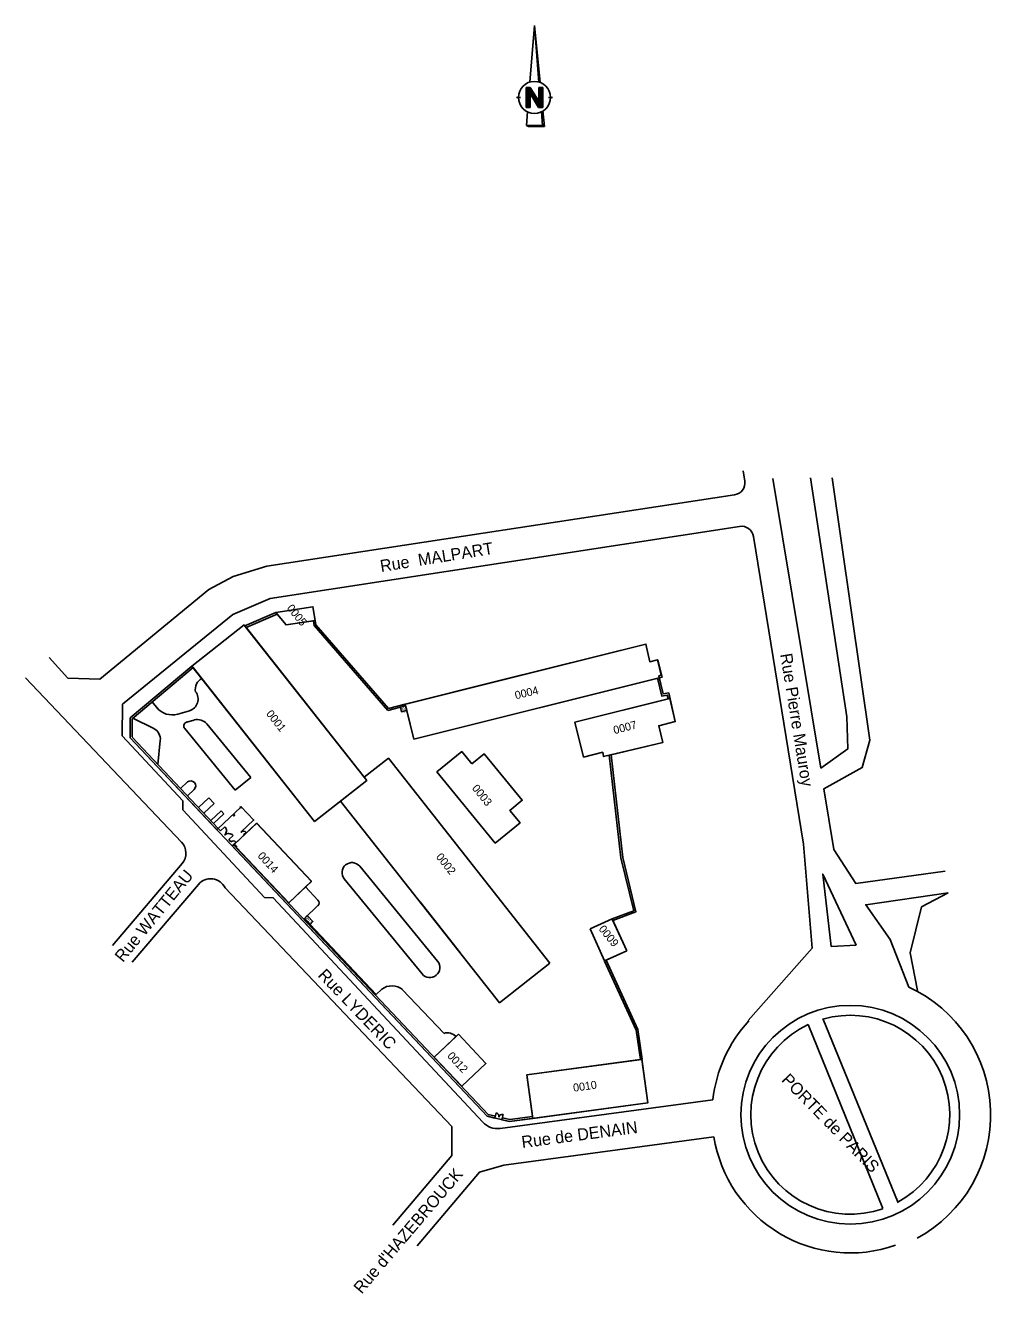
# Model space of a CAD drawing. Extents: x 704383 to 706615, y 7057567 to 7059313.
# Drawn here: x 704383.3 to 704624.5, y 7058894 to 7059210.9 of the extents above; entities that cross this region are included whole.
import ezdxf

# ---------------------------------------------------------------- set-up
doc = ezdxf.new("R2010")
doc.units = 0
for name, color, linetype in [('DH_HACHURE-MOTIF', 7, 'Continuous'), ('DH_NORD', 7, 'Continuous'), ('DH_TEXTE', 7, 'Continuous'), ('GEOSID_AIRE_AMENAGEE_POLYGONE', 7, 'Continuous'), ('GO_DALLE', 7, 'Continuous'), ('GO_MUR_EXTERIEUR', 7, 'Continuous'), ('IMM_LIMITE PHYSIQUE', 7, 'Continuous'), ('R_PLU_CANALISATION_CL_A', 7, 'Continuous'), ('SID_NUMERO_BATI', 7, 'Continuous'), ('SID_POLYLIGNES_BATI', 7, 'Continuous'), ('SID_POLYLIGNES_IMMEUBLE', 7, 'Continuous'), ('VOIRIE_BORDURE', 7, 'Continuous'), ('VOIRIE_ROUTE', 7, 'Continuous')]:
    doc.layers.add(name, color=color, linetype=linetype)

msp = doc.modelspace()

# ---------------------------------------------------------------- linework, layer by layer
at = {"layer": 'DH_HACHURE-MOTIF'}
for p, q in [((704524.38, 7058985.08), (704529.92, 7058987.58)), ((704527.99, 7058977.1), (704524.38, 7058985.08)), ((704533.53, 7058979.6), (704527.99, 7058977.1))]:
    msp.add_line(p, q, dxfattribs=at)
for points in [[(704455.24, 7059062.07), (704455.68, 7059062.15), (704455.11, 7059065.6), (704445.84, 7059064.17), (704446.16, 7059063.77), (704448.39, 7059061.05), (704455.24, 7059062.07)], [(704425.16, 7059050.42), (704427.36, 7059047.63), (704455.54, 7059011.91), (704462.02, 7059017.02), (704468.57, 7059022.2), (704467.95, 7059022.98), (704438.22, 7059060.67), (704437.91, 7059061.06), (704424.88, 7059050.77), (704425.16, 7059050.42)], [(704478.26, 7059040.81), (704478.55, 7059039.67), (704480.34, 7059032.52), (704541.99, 7059047.92), (704542.43, 7059048.03), (704541.28, 7059052.31), (704539.34, 7059051.83), (704538.31, 7059056.28), (704501.44, 7059047.07), (704478.16, 7059041.25), (704478.26, 7059040.81)], [(704527.54, 7059029.23), (704527.77, 7059028.16), (704542.53, 7059031.65), (704541.53, 7059035.87), (704545.67, 7059036.9), (704544.34, 7059042.69), (704543.9, 7059042.58), (704520.56, 7059036.75), (704522.74, 7059028.02), (704527.54, 7059029.23)], [(704514.34, 7058976.54), (704473.96, 7059027.72), (704467.95, 7059022.98), (704468.57, 7059022.2), (704462.02, 7059017.02), (704501.78, 7058966.63), (704514.34, 7058976.54)], [(704494.83, 7059026.3), (704492.3, 7059029.39), (704486.11, 7059024.32), (704500.68, 7059006.53), (704506.87, 7059011.6), (704504.34, 7059014.7), (704507.43, 7059017.23), (704497.92, 7059028.83), (704494.83, 7059026.3)], [(704453.78, 7058988.34), (704453.71, 7058988.42), (704452.98, 7058987.73), (704454.4, 7058986.22), (704455.13, 7058986.91), (704453.78, 7058988.34)], [(704529.92, 7058987.58), (704530, 7058987.39), (704533.53, 7058979.6)], [(704490.9, 7058958.2), (704485.43, 7058953.04), (704492.29, 7058945.77), (704498.34, 7058951.47), (704491.48, 7058958.75), (704490.9, 7058958.2)], [(704509.98, 7058938.19), (704510.04, 7058937.74), (704538.79, 7058941.6), (704537.32, 7058952.5), (704536.88, 7058952.44), (704508.58, 7058948.64), (704509.98, 7058938.19)]]:
    msp.add_lwpolyline(points, dxfattribs=at)
msp.add_lwpolyline([(704451.03, 7058993.45), (704454.75, 7058996.96), (704441.02, 7059011.5), (704435.51, 7059006.3), (704436.09, 7059005.68), (704435.92, 7059005.52), (704449.06, 7058991.59)], close=True, dxfattribs=at)
at = {"layer": 'DH_NORD'}
for p, q in [((704509.33, 7059196.7), (704510.47, 7059210.86)), ((704510.47, 7059210.86), (704511.6, 7059196.7)), ((704511.88, 7059196.6), (704510.47, 7059210.86)), ((704508.41, 7059195.36), (704509.42, 7059195.36)), ((704508.41, 7059190.35), (704508.41, 7059195.36)), ((704508.5, 7059190.35), (704508.5, 7059195.36)), ((704508.8, 7059190.35), (704508.8, 7059195.36)), ((704509.1, 7059190.35), (704509.1, 7059195.36)), ((704509.4, 7059190.35), (704509.4, 7059195.36)), ((704509.42, 7059195.36), (704511.53, 7059191.89)), ((704509.7, 7059193.34), (704509.7, 7059194.89)), ((704510, 7059192.85), (704510, 7059194.4)), ((704511.53, 7059191.89), (704511.53, 7059195.36)), ((704511.53, 7059195.36), (704512.53, 7059195.36)), ((704511.8, 7059190.35), (704511.8, 7059195.36)), ((704512.1, 7059190.35), (704512.1, 7059195.36)), ((704512.4, 7059190.35), (704512.4, 7059195.36)), ((704512.53, 7059195.36), (704512.53, 7059190.35)), ((704505.97, 7059192.86), (704506.97, 7059192.86)), ((704511.52, 7059190.35), (704509.41, 7059193.82)), ((704509.41, 7059193.82), (704509.41, 7059190.35)), ((704510.3, 7059192.36), (704510.3, 7059193.91)), ((704510.6, 7059191.86), (704510.6, 7059193.42)), ((704510.9, 7059191.37), (704510.9, 7059192.93)), ((704511.2, 7059190.88), (704511.2, 7059192.43)), ((704511.5, 7059190.39), (704511.5, 7059191.94)), ((704513.97, 7059192.86), (704514.97, 7059192.86)), ((704509.41, 7059190.35), (704508.41, 7059190.35)), ((704508.47, 7059185.86), (704508.74, 7059189.25)), ((704512.53, 7059190.35), (704511.52, 7059190.35)), ((704512.2, 7059189.25), (704512.47, 7059185.86)), ((704512.97, 7059185.61), (704512.58, 7059189.47)), ((704508.47, 7059185.86), (704512.47, 7059185.86)), ((704508.97, 7059185.61), (704508.47, 7059185.86)), ((704508.97, 7059185.61), (704512.97, 7059185.61)), ((704512.97, 7059185.61), (704512.47, 7059185.86))]:
    msp.add_line(p, q, dxfattribs=at)
msp.add_circle((704510.47, 7059192.86), 4, dxfattribs=at)
at = {"layer": 'GEOSID_AIRE_AMENAGEE_POLYGONE'}
msp.add_lwpolyline([(704477.29, 7059039.35), (704477, 7059040.5), (704478.26, 7059040.81), (704478.54, 7059039.67)], close=True, dxfattribs=at)
at = {"layer": 'GO_DALLE'}
msp.add_lwpolyline([(704478.26, 7059040.81), (704478.55, 7059039.67), (704477.29, 7059039.35), (704477, 7059040.5)], close=True, dxfattribs=at)
at = {"layer": 'GO_MUR_EXTERIEUR'}
for p, q in [((704455.11, 7059065.6), (704445.84, 7059064.17)), ((704455.68, 7059062.15), (704455.11, 7059065.6)), ((704445.84, 7059064.17), (704448.39, 7059061.05)), ((704448.39, 7059061.05), (704455.68, 7059062.15)), ((704424.88, 7059050.77), (704437.91, 7059061.06)), ((704437.91, 7059061.06), (704468.57, 7059022.2)), ((704538.31, 7059056.28), (704478.16, 7059041.25)), ((704539.34, 7059051.83), (704538.31, 7059056.28)), ((704541.28, 7059052.31), (704539.34, 7059051.83)), ((704542.43, 7059048.03), (704541.28, 7059052.31)), ((704455.54, 7059011.91), (704424.88, 7059050.77)), ((704480.34, 7059032.52), (704542.43, 7059048.03)), ((704520.56, 7059036.75), (704544.34, 7059042.69)), ((704544.34, 7059042.69), (704545.67, 7059036.9)), ((704478.16, 7059041.25), (704480.34, 7059032.52)), ((704522.74, 7059028.02), (704520.56, 7059036.75)), ((704545.67, 7059036.9), (704541.53, 7059035.87)), ((704541.53, 7059035.87), (704542.53, 7059031.65)), ((704473.96, 7059027.72), (704467.95, 7059022.98)), ((704514.34, 7058976.54), (704473.96, 7059027.72)), ((704486.11, 7059024.32), (704492.3, 7059029.39)), ((704492.3, 7059029.39), (704494.83, 7059026.3)), ((704494.83, 7059026.3), (704497.92, 7059028.83)), ((704497.92, 7059028.83), (704507.43, 7059017.23)), ((704500.68, 7059006.53), (704486.11, 7059024.32)), ((704468.57, 7059022.2), (704455.54, 7059011.91)), ((704468.57, 7059022.2), (704462.02, 7059017.02)), ((704467.95, 7059022.98), (704468.57, 7059022.2)), ((704462.02, 7059017.02), (704501.78, 7058966.63)), ((704507.43, 7059017.23), (704504.34, 7059014.7)), ((704504.34, 7059014.7), (704506.87, 7059011.6)), ((704441.06, 7059011.54), (704435.51, 7059006.3)), ((704454.78, 7058996.99), (704441.06, 7059011.54)), ((704506.87, 7059011.6), (704500.68, 7059006.53)), ((704449.06, 7058991.59), (704454.78, 7058996.99)), ((704452.98, 7058987.73), (704453.71, 7058988.42)), ((704453.71, 7058988.42), (704455.13, 7058986.91)), ((704454.4, 7058986.22), (704452.98, 7058987.73)), ((704455.13, 7058986.91), (704454.4, 7058986.22)), ((704524.38, 7058985.08), (704529.92, 7058987.58)), ((704529.92, 7058987.58), (704533.53, 7058979.6)), ((704527.99, 7058977.1), (704524.38, 7058985.08)), ((704533.53, 7058979.6), (704527.99, 7058977.1)), ((704501.78, 7058966.63), (704514.34, 7058976.54)), ((704485.43, 7058953.04), (704491.48, 7058958.75)), ((704491.48, 7058958.75), (704498.34, 7058951.47)), ((704492.29, 7058945.77), (704485.43, 7058953.04)), ((704498.34, 7058951.47), (704492.29, 7058945.77)), ((704508.58, 7058948.64), (704537.32, 7058952.5)), ((704537.32, 7058952.5), (704538.79, 7058941.6)), ((704510.04, 7058937.74), (704508.58, 7058948.64)), ((704538.79, 7058941.6), (704510.04, 7058937.74))]:
    msp.add_line(p, q, dxfattribs=at)
for points in [[(704542.53, 7059031.65), (704527.77, 7059028.16), (704527.54, 7059029.23), (704522.74, 7059028.02)], [(704435.51, 7059006.3), (704436.09, 7059005.68), (704435.92, 7059005.52), (704449.06, 7058991.59)]]:
    msp.add_lwpolyline(points, dxfattribs=at)
at = {"layer": 'IMM_LIMITE PHYSIQUE'}
for p, q in [((704438.13, 7059060.8), (704445.86, 7059064.13)), ((704438.43, 7059060.44), (704446.16, 7059063.77)), ((704455.24, 7059062.07), (704455.44, 7059060.88)), ((704455.68, 7059062.15), (704455.86, 7059061.08)), ((704455.44, 7059060.88), (704473.82, 7059039.69)), ((704455.86, 7059061.08), (704473.97, 7059040.2)), ((704424.88, 7059050.77), (704409.46, 7059037.8)), ((704425.17, 7059050.42), (704409.91, 7059037.59)), ((704478.27, 7059040.81), (704473.82, 7059039.69)), ((704478.16, 7059041.25), (704473.97, 7059040.2)), ((704409.46, 7059037.8), (704409.46, 7059032.85)), ((704409.91, 7059037.59), (704409.91, 7059033.05)), ((704545.19, 7059037.4), (704545.19, 7059037.4)), ((704409.46, 7059032.85), (704431.13, 7059009.88)), ((704409.92, 7059033.01), (704431.45, 7059010.19)), ((704431.45, 7059010.19), (704437.02, 7059015.43)), ((704432.01, 7059009.6), (704433.1, 7059010.63)), ((704437.1, 7059009.3), (704440.31, 7059012.33)), ((704431.45, 7059010.19), (704431.13, 7059009.88)), ((704431.46, 7059010.18), (704432.01, 7059009.6)), ((704434.07, 7059007.42), (704435.16, 7059008.45)), ((704434.07, 7059007.42), (704434.62, 7059006.83)), ((704437.1, 7059009.3), (704437.16, 7059009.24)), ((704438.43, 7059009.2), (704437.78, 7059008.58)), ((704437.78, 7059008.58), (704437.84, 7059008.52)), ((704435.29, 7059006.12), (704434.97, 7059005.81)), ((704434.97, 7059005.81), (704498.66, 7058938.29)), ((704435.89, 7059006.8), (704435.23, 7059006.18)), ((704435.23, 7059006.18), (704435.29, 7059006.12)), ((704435.29, 7059006.12), (704498.9, 7058938.69)), ((704500.59, 7058937.83), (704498.66, 7058938.29)), ((704500.7, 7058938.27), (704498.9, 7058938.69)), ((704500.59, 7058937.83), (704500.9, 7058939.12)), ((704502.35, 7058937.42), (704502.65, 7058938.71)), ((704504.3, 7058937.43), (704502.45, 7058937.86)), ((704510.04, 7058937.74), (704504.28, 7058936.97)), ((704509.98, 7058938.19), (704504.3, 7058937.43)), ((704504.28, 7058936.97), (704502.35, 7058937.42))]:
    msp.add_line(p, q, dxfattribs=at)
for points in [[(704541.24, 7059047.74), (704542.29, 7059043.26), (704543.68, 7059043.53), (704543.9, 7059042.59)], [(704541.68, 7059047.84), (704542.63, 7059043.79), (704544.03, 7059044.06), (704544.34, 7059042.69)], [(704529.16, 7059028.54), (704532.08, 7059002.82), (704535.3, 7058989.65), (704529.92, 7058987.59)], [(704529.61, 7059028.59), (704532.53, 7059002.9), (704535.84, 7058989.37), (704530.09, 7058987.17)], [(704536.94, 7058952.45), (704535.91, 7058959.79), (704528.01, 7058977.07)], [(704537.38, 7058952.51), (704536.35, 7058959.92), (704528.42, 7058977.26)]]:
    msp.add_lwpolyline(points, dxfattribs=at)
for points in [[(704435.14, 7059013.52), (704435.35, 7059013.3), (704435.59, 7059013.53), (704435.38, 7059013.75)], [(704437.18, 7059015.58), (704436.93, 7059015.53), (704437.1, 7059015.34)], [(704437.18, 7059015.58), (704440.34, 7059012.23), (704440.37, 7059012.27), (704437.21, 7059015.62)]]:
    msp.add_lwpolyline(points, close=True, dxfattribs=at)
for centre, radius, start, end in [((704432.01, 7059009.6), 1.5, 313.3307, 43.3307), ((704434.07, 7059007.42), 1.5, 43.3307, 133.3307), ((704437.78, 7059008.58), 0.9, 43.3307, 133.3307), ((704435.23, 7059006.18), 0.9, 43.3307, 133.3307), ((704500.72, 7058938.26), 0.874, 346.7916, 78.7098), ((704502.43, 7058937.87), 0.874, 75.2683, 166.7916)]:
    msp.add_arc(centre, radius, start, end, dxfattribs=at)
at = {"layer": 'R_PLU_CANALISATION_CL_A'}
msp.add_line((704481.9, 7058991.83), (704492.02, 7058979), dxfattribs=at)
at = {"layer": 'SID_POLYLIGNES_BATI'}
for p, q in [((704455.11, 7059065.6), (704445.84, 7059064.17)), ((704455.68, 7059062.15), (704455.11, 7059065.6)), ((704445.84, 7059064.17), (704448.39, 7059061.05)), ((704448.39, 7059061.05), (704455.68, 7059062.15)), ((704424.88, 7059050.77), (704437.91, 7059061.06)), ((704437.91, 7059061.06), (704468.57, 7059022.2)), ((704538.31, 7059056.28), (704478.16, 7059041.25)), ((704539.34, 7059051.83), (704538.31, 7059056.28)), ((704541.28, 7059052.31), (704539.34, 7059051.83)), ((704542.43, 7059048.03), (704541.28, 7059052.31)), ((704455.54, 7059011.91), (704424.88, 7059050.77)), ((704480.34, 7059032.52), (704542.43, 7059048.03)), ((704478.16, 7059041.25), (704480.34, 7059032.52)), ((704473.96, 7059027.72), (704467.95, 7059022.98)), ((704514.34, 7058976.54), (704473.96, 7059027.72)), ((704486.11, 7059024.32), (704492.3, 7059029.39)), ((704492.3, 7059029.39), (704494.83, 7059026.3)), ((704494.83, 7059026.3), (704497.92, 7059028.83)), ((704497.92, 7059028.83), (704507.43, 7059017.23)), ((704500.68, 7059006.53), (704486.11, 7059024.32)), ((704468.57, 7059022.2), (704455.54, 7059011.91)), ((704468.57, 7059022.2), (704462.02, 7059017.02)), ((704467.95, 7059022.98), (704468.57, 7059022.2)), ((704462.02, 7059017.02), (704501.78, 7058966.63)), ((704507.43, 7059017.23), (704504.34, 7059014.7)), ((704504.34, 7059014.7), (704506.87, 7059011.6)), ((704441.02, 7059011.5), (704435.51, 7059006.3)), ((704454.75, 7058996.96), (704441.02, 7059011.5)), ((704506.87, 7059011.6), (704500.68, 7059006.53)), ((704449.06, 7058991.59), (704454.75, 7058996.96)), ((704452.98, 7058987.73), (704453.71, 7058988.42)), ((704453.71, 7058988.42), (704455.13, 7058986.91)), ((704454.4, 7058986.22), (704452.98, 7058987.73)), ((704455.13, 7058986.91), (704454.4, 7058986.22)), ((704524.38, 7058985.08), (704529.92, 7058987.58)), ((704529.92, 7058987.58), (704533.53, 7058979.6)), ((704527.99, 7058977.1), (704524.38, 7058985.08)), ((704533.53, 7058979.6), (704527.99, 7058977.1)), ((704501.78, 7058966.63), (704514.34, 7058976.54)), ((704485.43, 7058953.04), (704491.48, 7058958.75)), ((704491.48, 7058958.75), (704498.34, 7058951.47)), ((704492.29, 7058945.77), (704485.43, 7058953.04)), ((704498.34, 7058951.47), (704492.29, 7058945.77)), ((704508.58, 7058948.64), (704537.32, 7058952.5)), ((704537.32, 7058952.5), (704538.79, 7058941.6)), ((704510.04, 7058937.74), (704508.58, 7058948.64)), ((704538.79, 7058941.6), (704510.04, 7058937.74))]:
    msp.add_line(p, q, dxfattribs=at)
msp.add_lwpolyline([(704477.29, 7059039.35), (704477, 7059040.5), (704478.26, 7059040.81), (704478.55, 7059039.67)], close=True, dxfattribs=at)
msp.add_lwpolyline([(704435.51, 7059006.3), (704436.09, 7059005.68), (704435.92, 7059005.52), (704449.06, 7058991.59)], dxfattribs=at)
at = {"layer": 'SID_POLYLIGNES_IMMEUBLE'}
for p, q in [((704473.97, 7059040.2), (704538.31, 7059056.28)), ((704538.31, 7059056.28), (704539.34, 7059051.83)), ((704539.34, 7059051.83), (704541.24, 7059052.31)), ((704473.97, 7059040.2), (704473.97, 7059040.2)), ((704409.46, 7059032.85), (704409.46, 7059037.8)), ((704545.67, 7059036.9), (704541.53, 7059035.87)), ((704541.53, 7059035.87), (704542.53, 7059031.65)), ((704498.66, 7058938.29), (704409.46, 7059032.85)), ((704542.53, 7059031.65), (704529.61, 7059028.6)), ((704535.84, 7058989.37), (704530.09, 7058987.17)), ((704530.09, 7058987.17), (704533.53, 7058979.6)), ((704533.53, 7058979.6), (704528.42, 7058977.26)), ((704528.42, 7058977.26), (704536.35, 7058959.92)), ((704536.35, 7058959.92), (704538.79, 7058941.6))]:
    msp.add_line(p, q, dxfattribs=at)
for points in [[(704437.91, 7059061.06), (704438.13, 7059060.8), (704445.86, 7059064.13), (704445.84, 7059064.17), (704455.11, 7059065.6)], [(704455.11, 7059065.6), (704455.87, 7059061.07), (704473.97, 7059040.2)], [(704409.46, 7059037.8), (704424.88, 7059050.77), (704437.91, 7059061.06)], [(704541.24, 7059052.31), (704542.14, 7059048.47), (704541.57, 7059048.32), (704542.63, 7059043.79), (704544.03, 7059044.06), (704545.67, 7059036.9)], [(704529.61, 7059028.6), (704532.53, 7059002.9), (704535.84, 7058989.37)], [(704538.79, 7058941.6), (704504.28, 7058936.97), (704498.66, 7058938.29)]]:
    msp.add_lwpolyline(points, dxfattribs=at)
at = {"layer": 'VOIRIE_BORDURE'}
for p, q in [((704414.91, 7059041.8), (704416.34, 7059040.07)), ((704421.34, 7059038.77), (704424.26, 7059039.62)), ((704410.1, 7059037.75), (704415.32, 7059035.18)), ((704420.6, 7059038.55), (704420.6, 7059038.55)), ((704423.56, 7059036.75), (704425.43, 7059037.29)), ((704428.59, 7059036.32), (704439.56, 7059022.94)), ((704423.07, 7059035.17), (704435.69, 7059019.77)), ((704416.38, 7059026.17), (704416.97, 7059032.19)), ((704422.04, 7059020.17), (704423.78, 7059021.81)), ((704435.69, 7059019.77), (704439.56, 7059022.94)), ((704423.75, 7059018.35), (704425.41, 7059019.91)), ((704426.5, 7059015.44), (704429.08, 7059017.87)), ((704430.45, 7059016.42), (704429.08, 7059017.87)), ((704427.87, 7059013.98), (704430.45, 7059016.42)), ((704429.59, 7059012.17), (704432.17, 7059014.6)), ((704430.27, 7059011.44), (704432.85, 7059013.87)), ((704432.85, 7059013.87), (704432.17, 7059014.6)), ((704466.81, 7059000.75), (704486.26, 7058977.01)), ((704453.29, 7058995.58), (704456.38, 7058992.31)), ((704462.95, 7058997.58), (704482.4, 7058973.84)), ((704456.34, 7058990.9), (704452.98, 7058987.73)), ((704452.98, 7058987.73), (704470.91, 7058968.72)), ((704470.91, 7058968.72), (704472.31, 7058970.04)), ((704477.53, 7058969.89), (704487.81, 7058959))]:
    msp.add_line(p, q, dxfattribs=at)
for centre, radius, start, end in [((704428.71, 7059044.99), 3, 115.4761, 192.4737), ((704423.41, 7059042.5), 3, 286.3025, 37.942), ((704419.94, 7059043.57), 5, 219.5679, 286.3025), ((704423.84, 7059035.79), 1, 106.0656, 219.3307), ((704426.26, 7059034.41), 3, 39.3307, 106.0656), ((704413.99, 7059032.49), 3, 354.3306, 63.7442), ((704424.57, 7059020.84), 1.25, 312.1096, 129.3307), ((704464.88, 7058999.16), 2.5, 39.3307, 219.3307), ((704455.65, 7058991.62), 1, 313.3306, 43.3306), ((704484.33, 7058975.43), 2.5, 219.3307, 39.3307), ((704488.72, 7058956.14), 3, 43.3308, 107.6513)]:
    msp.add_arc(centre, radius, start, end, dxfattribs=at)
msp.add_ellipse((704474.83, 7058967.86), major_axis=(-3.68, 0), ratio=0.816097, start_param=3.897855, end_param=5.468654, dxfattribs=at)
at = {"layer": 'VOIRIE_ROUTE'}
for p, q in [((704422.29, 7059006.78), (704383.25, 7059047.84)), ((704401.89, 7059047.5), (704393.87, 7059047.71)), ((704407.51, 7059041.29), (704407.46, 7059033.34)), ((704407.46, 7059033.34), (704422.64, 7059017.07)), ((704422.57, 7059014.87), (704422.64, 7059017.07)), ((704422.57, 7059014.87), (704443.04, 7058992.94)), ((704405.06, 7058980.96), (704422.44, 7059001.43)), ((704409.98, 7058976.78), (704426.49, 7058996.23)), ((704489.86, 7058935.68), (704433.16, 7058995.35)), ((704443.04, 7058992.94), (704445.28, 7058992.87)), ((704445.22, 7058992.87), (704497.55, 7058936.8)), ((704579.84, 7058980.27), (704563.88, 7058962.24)), ((704590.86, 7058981.06), (704584.66, 7058980.69)), ((704578.87, 7058961.23), (704597.53, 7058915.24)), ((704582.5, 7058962.71), (704601.33, 7058916.61)), ((704489.86, 7058935.68), (704489.83, 7058928.47)), ((704475.1, 7058911.09), (704489.83, 7058928.47))]:
    msp.add_line(p, q, dxfattribs=at)
for points in [[(704563.05, 7059097.01), (704562.66, 7059099.55)], [(704570.06, 7059097.64), (704582.05, 7059025.29), (704588.75, 7059030.06), (704588.5, 7059038.06), (704579.47, 7059097.77)], [(704584.89, 7059097.77), (704594.3, 7059032.25), (704592.36, 7059025.42), (704582.83, 7059020.13), (704585.27, 7059004.91), (704590.82, 7058996.4), (704613.12, 7058999.53)], [(704401.89, 7059047.5), (704429.11, 7059069.87), (704435.15, 7059073.16), (704443.6, 7059075.7), (704560.49, 7059093.54)], [(704561.75, 7059085.66), (704444.46, 7059067.63), (704435.1, 7059063.67), (704407.51, 7059041.29)], [(704579.84, 7058980.27), (704577.69, 7059006.28), (704565.22, 7059083.13)], [(704393.87, 7059047.71), (704389.19, 7059052.94)], [(704584.66, 7058980.69), (704582.51, 7058998.8), (704590.86, 7058981.06)], [(704613.89, 7058994.08), (704593.27, 7058991.11), (704599.4, 7058982.44), (704604, 7058970.55)], [(704613.89, 7058994.08), (704607.19, 7058990.6), (704604.35, 7058979.12), (704606.2, 7058969.71)], [(704501.87, 7058935.26), (704555.07, 7058942.41)], [(704481.17, 7058905.94), (704496.73, 7058924.28), (704502.79, 7058926.09), (704555.31, 7058933.15)]]:
    msp.add_lwpolyline(points, dxfattribs=at)
msp.add_circle((704589.4, 7058938.66), 27.33, dxfattribs=at)
for centre, radius, start, end in [((704560.03, 7059096.55), 3.05, 278.6767, 8.6767), ((704562.21, 7059082.65), 3.05, 9.2218, 98.7403), ((704419.39, 7059004.02), 4, 319.6675, 43.547), ((704429.54, 7058993.64), 4, 25.2763, 139.6675), ((704589.4, 7058938.66), 35.08, 298.459, 65.3951), ((704589.4, 7058938.66), 24.85, 298.459, 105.9703), ((704589.4, 7058938.66), 34.53, 137.2612, 173.7773), ((704589.4, 7058938.66), 24.85, 115.0132, 289.1455), ((704501.2, 7058940.21), 5, 223.0213, 277.6524), ((704589.4, 7058938.66), 34.53, 189.1939, 289.1455)]:
    msp.add_arc(centre, radius, start, end, dxfattribs=at)

# ---------------------------------------------------------------- texts
at = {"layer": 'DH_TEXTE'}
for s, rotation, p in [('Rue  MALPART', 9.1668, (704472.16, 7059074.25)), ('Rue Pierre Mauroy', 279.2071, (704571.87, 7059053.71)), ('Rue WATTEAU', 50.7423, (704407.64, 7058976.56)), ('Rue LYDERIC', 313.8024, (704456.17, 7058973.36)), ('PORTE de PARIS', 314.4253, (704572.02, 7058947.17)), ('Rue de DENAIN', 7.4746, (704507.44, 7058930.32)), ("Rue d'HAZEBROUCK", 49.6268, (704467.29, 7058893.71))]:
    msp.add_text(s, height=3, rotation=rotation, dxfattribs=at).set_placement(p)
at = {"layer": 'SID_NUMERO_BATI'}
for s, height, rotation, p in [('0005', 2, 309.3307, (704448.46, 7059065.18)), ('0004', 2, 13.5243, (704505.84, 7059042.44)), ('0001', 2, 308.2727, (704443.3, 7059038.81)), ('0021', 0.702, 308.0308, (704476.7, 7059040.79)), ('0007', 2, 14.5051, (704530.47, 7059033.74)), ('0003', 2, 309.3307, (704494.73, 7059020.18)), ('0014', 2, 312.5129, (704441.16, 7059003.23)), ('0002', 2, 308.2727, (704485.75, 7059003.06)), ('0013', 0.698, 312.5129, (704453.03, 7058987.91)), ('0009', 2, 309.3307, (704526.39, 7058985)), ('0012', 2, 312.5129, (704488.55, 7058953.26)), ('0010', 2, 8.0003, (704520.28, 7058944.39))]:
    msp.add_text(s, height=height, rotation=rotation, dxfattribs=at).set_placement(p)

doc.saveas('drawing.dxf')
